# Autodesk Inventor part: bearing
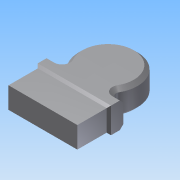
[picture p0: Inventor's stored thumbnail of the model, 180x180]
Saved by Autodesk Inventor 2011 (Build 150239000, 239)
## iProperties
Created: 2020-12
Part Number: bearing
Document SubType Name: Modeling
Designer: PC
Density: 1 g/cm^3
Author: PC
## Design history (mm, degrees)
sketch "Sketch1"
  geometry: L1 (0, 15.508)-(0, -23.872); L2 (-50, -29.013)-(50, -29.013); L3 (50, -29.013)-(50, -49.013); L4 (50, -49.013)-(-50, -49.013); L5 (-50, -49.013)-(-50, -29.013); C1 r 40 at (0, 0); 2 further points
  constraints: 10 end point, 2 parallel, 2 point on line, 1 centre point, 1 coincident, 1 horizontal, 1 midpoint, 1 perpendicular, 1 vertical
  dimensions: "d0" = 20 distance between parallel lines of L4 L2; "d1" = 100 distance of L3.end L4.end; "d2" = 80 diameter of C1
extrude "Extrusion1" new body sketch "Sketch1" distance "d3" = 35; taper "d4" = 0 deg
fillet "Fillet1" dims "d5" = 6
chamfer "Chamfer1" distance "d6" = 5; stored, may be unused: second distance "d7" = 2, angle "d8" = 45 deg
chamfer "Chamfer2" distance "d9" = 3; stored, may be unused: second distance "d10" = 2, angle "d11" = 45 deg
sketch "Sketch2"
  geometry: L1 (94, 0)-(94, -29) reference; L2 (0, 0)-(94, 0) reference; L3 (0, -29)-(0, 0) reference; L4 (94, -29)-(0, -29) reference; 1 further point
extrude "Extrusion2" join sketch "Sketch2" distance "d12" = 40; taper "d13" = 0 deg
body "Solid1"
